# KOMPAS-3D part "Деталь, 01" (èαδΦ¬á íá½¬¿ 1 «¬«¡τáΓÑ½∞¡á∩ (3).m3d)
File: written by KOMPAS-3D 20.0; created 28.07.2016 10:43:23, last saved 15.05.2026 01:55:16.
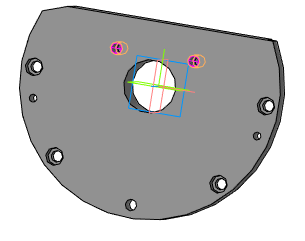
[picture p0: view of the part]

Document properties: Полное имя файла: E:\test_kompas\all_v18\Крышка балки 1 окончательная (3).m3d

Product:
- Part/product: Деталь  | designation 01
    Масса: 9.68884
  - Body: Тело 1
- Part/product: Деталь
    Масса: 9.68884
  - Body: Тело 1

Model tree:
1. Эскиз:1
2. Операция выдавливания:1
     Расстояние 1 = 40
3. Эскиз:2  (with: Операция выдавливания:1)
4. Элемент выдавливания:2
     Расстояние 2 = 20
5. Эскиз:13  (with: Операция выдавливания:1)
6. Элемент выдавливания:5
     Расстояние 2 = 40
7. Эскиз:14  (with: Операция выдавливания:1)
8. Эскиз:15  (with: Операция выдавливания:1, Элемент выдавливания:2)
9. Элемент выдавливания:6
     Расстояние 2 = 40
10. Эскиз:16  (with: Операция выдавливания:1, Элемент выдавливания:2)
11. Элемент выдавливания:7
     Расстояние 2 = 11
12. Отверстие:3  (with: Операция выдавливания:1)  (labels: M12)
     Глубина выреза = 30; Диаметр отверстия = 10.1056; Угол конуса дна = 118; Расстояние 1 = 31; Расстояние 2 = 46.4075
13. M12  (with: Отверстие:3, Операция выдавливания:1)  (labels: M12; cil0_24705-2004 coarse)
     Длина резьбы = 25; Шаг резьбы = 1.75; Номинальный диаметр резьбы = 12
14. Отверстие:4  (with: Операция выдавливания:1, M12)  (labels: M12; cil0_24705-2004 coarse)
     Глубина выреза = 30; Диаметр отверстия = 10.1056; Угол конуса дна = 118; Расстояние 1 = 31; Расстояние 2 = 70.8326; Длина резьбы = 25; Шаг резьбы = 1.75; Номинальный диаметр резьбы = 12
